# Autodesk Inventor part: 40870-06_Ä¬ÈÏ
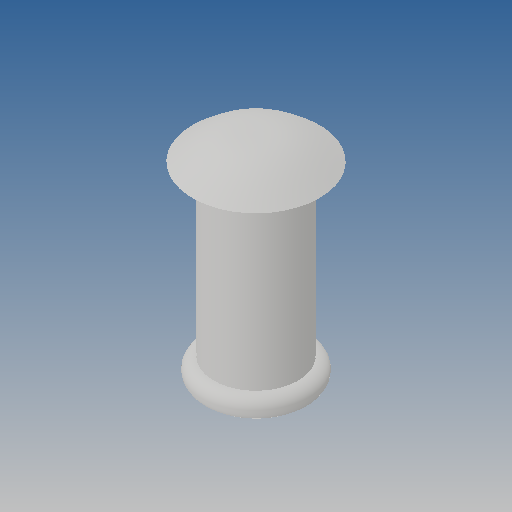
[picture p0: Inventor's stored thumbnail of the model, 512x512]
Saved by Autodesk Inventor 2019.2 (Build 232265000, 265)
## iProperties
Created: 2010-06
Part Number: 40870-06_Ä¬ÈÏ
Material: Ogólny
Document SubType Name: Modeling
Designer: CADENGINEERING4
Density: 1 g/cm^3
Appearance: Domyślna
Author: CADENGINEERING4
Revision Number: ÈÎºÎ
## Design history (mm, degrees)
feature "NONE"
node "Bryła1"
